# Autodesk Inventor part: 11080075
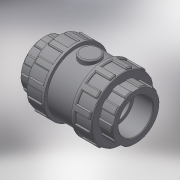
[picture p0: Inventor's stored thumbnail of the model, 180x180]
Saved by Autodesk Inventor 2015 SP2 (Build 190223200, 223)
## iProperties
Created: 2017-11
Part Number: 11080075
Material: Generic
Description: PLASSON CHECK VALVE CEM 75 PTFE COATED SPRING + EPDM O-RING
Document SubType Name: Modeling
Designer: KIM
Density: 1 g/cm^3
Appearance: Default
Author: KIM
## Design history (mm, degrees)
derived "110800 - 110600 110900-110000.ipt"
feature "Solid1::110800 - 110600 110900-110000.ipt"
tag "TaggingFeature1"
body "Solid1"
other parameters: "d0" = 215, "d1" = 75, "d2" = 139, "d3" = 44, "d5" = 30.8, "d7" = 105, "d8" = 125.1, "d13" = 2.25, "d23" = 44, "d24" = 133.44, "d25" = 1.5, "d26" = 2.25, "d27" = 20.85, "d28" = 10.425, "d29" = 33, "d30" = 0, "d35" = 2.25, "d39" = 69.5, "d45" = 360 deg, "d47" = 1.5, "d50" = 69.5, "d51" = 41.7, "d53" = 0, "d54" = 2.78, "d55" = 15, "d56" = 7.5, "d57" = 30.8, "d58" = 0, "d59" = 2.25, "d61" = 360 deg, "d_" = 75, "l_" = 44, "H_" = 215, "K_" = 139
